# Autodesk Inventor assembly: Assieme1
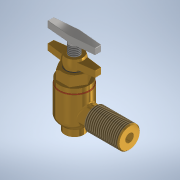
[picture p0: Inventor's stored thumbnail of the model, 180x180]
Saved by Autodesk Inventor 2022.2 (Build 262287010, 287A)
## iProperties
Created: 2022-03
Part Number: Assieme1
Document SubType Name: Assembly
Designer: 18619647
Author: 18619647
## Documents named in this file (8)
- D:\scuola\impianti disegno\inventor\valvola\Assieme1.iam
- D:\scuola\impianti disegno\inventor\valvola\cassa1.ipt
- D:\scuola\impianti disegno\inventor\valvola\coperchio.ipt
- D:\scuola\impianti disegno\inventor\valvola\maniglia.ipt
- D:\scuola\impianti disegno\inventor\valvola\otturatore.ipt
- D:\scuola\impianti disegno\inventor\valvola\stelo con impugnatura.ipt
- D:\scuola\impianti disegno\inventor\valvola\anello rame ricotto.ipt
- D:\scuola\impianti disegno\inventor\valvola\guarnizione gomma.ipt
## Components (7 placed, 7 different names)
1. cassa1:1 — Coincidente:1, Coincidente:2, Coincidente:3, Coincidente:4, Angolo:1, Angolo:2, Coincidente:6, Coincidente:9, Angolo:3, Angolo:4
2. coperchio:1 — Coincidente:3, Coincidente:4, Angolo:1, Coincidente:5, Coincidente:7, Coincidente:8, Allineato:1
3. maniglia:1 — Coincidente:10, Coincidente:11, Angolo:4
4. otturatore:1 — Coincidente:1, Coincidente:2, Angolo:2
5. stelo con impugnatura:1 — Coincidente:9, Allineato:1, Angolo:3, Coincidente:11
6. anello rame ricotto:1 — Coincidente:5, Coincidente:6
7. guarnizione gomma:1 — Coincidente:7, Coincidente:8, Coincidente:10
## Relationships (16: Mate 11, Angle 4, Flush 1)
- Coincidente:1 [Mate]: cassa1:1 ↔ otturatore:1
- Coincidente:2 [Mate]: cassa1:1 ↔ otturatore:1
- Coincidente:3 [Mate]: cassa1:1 ↔ coperchio:1
- Coincidente:4 [Mate]: cassa1:1 ↔ coperchio:1
- Angolo:1 [Angle]: cassa1:1 ↔ coperchio:1
- Angolo:2 [Angle]: cassa1:1 ↔ otturatore:1
- Coincidente:5 [Mate]: coperchio:1 ↔ anello rame ricotto:1
- Coincidente:6 [Mate]: cassa1:1 ↔ anello rame ricotto:1
- Coincidente:7 [Mate]: coperchio:1 ↔ guarnizione gomma:1
- Coincidente:8 [Mate]: coperchio:1 ↔ guarnizione gomma:1
- Coincidente:9 [Mate]: cassa1:1 ↔ stelo con impugnatura:1
- Allineato:1 [Flush]: coperchio:1 ↔ stelo con impugnatura:1
- Angolo:3 [Angle]: cassa1:1 ↔ stelo con impugnatura:1
- Coincidente:10 [Mate]: maniglia:1 ↔ guarnizione gomma:1
- Coincidente:11 [Mate]: maniglia:1 ↔ stelo con impugnatura:1
- Angolo:4 [Angle]: cassa1:1 ↔ maniglia:1
